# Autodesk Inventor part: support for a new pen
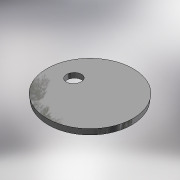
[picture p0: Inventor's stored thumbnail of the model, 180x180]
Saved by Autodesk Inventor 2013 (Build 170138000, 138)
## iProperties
Shininess: 64.0
Length Units: 11269
Angle Units: 11279
Time Units: 11290
Mass Units: 11283
Length Display Precision: 3
Angle Display Precision: 2
Compacted: True
Part Number: support for a new pen
Document SubType Name: Листовой материал
Created: 2005-02
Material: Stainless Steel, 440C
Designer: =<Author>
Manufacturer: Standard
Standards Organization: Custom
Description: =<Part Number>
Density: 7.75 g/cm^3
Sheet Metal Rule: По умолчанию
Mass: 44.1722 g
Surface Area: 43.5582 cm^2
Volume: 5.69963 cm^3
Density: 0.0
Volumn: 0.0
Area: 0.0
PropertySet Name: Model Information
Control State: 0
Master: False
Checked Out: False
Checked Out Date: 2008-10-15
Last Check In Date: 2008-10-15
Author: PVitaliy
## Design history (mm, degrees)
node "Грань1"
body "Solid1"
sketch "Эскиз1"
  geometry: L1 (0, 0)-(-10, 0); C1 r 25 at (0, 0); C2 r 4.5 at (-10, 0)
  constraints: 2 centre point, 2 coincident, 2 end point, 1 horizontal, 1 other
  dimensions: "d0" = 50 diameter of C1; "d5" = 9 diameter of C2; "d6" = 10 distance of L1.start L1.end
feature "Пластина1" dims "Толщина" = 3
other parameters: "Радиус_гибки" = 3 (= Толщина), "Ширина_просечки" = 3 (= Толщина), "Глубина_просечки" = 1.5 (= 0.5 x Толщина), "Размер_высечки" = 12 (= 4 x Толщина), "Зазор_стыка" = 0.01, "Минимальный_остаток" = 6 (= 2 x Толщина), "Радиус_перехода" = 3 (= Радиус_гибки), "d4" = 3 (= Радиус_гибки), "JacobiRadiusSize" = 3 (= Толщина), "GapSize" = 3 (= Толщина)
